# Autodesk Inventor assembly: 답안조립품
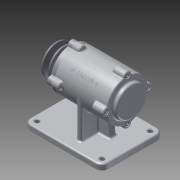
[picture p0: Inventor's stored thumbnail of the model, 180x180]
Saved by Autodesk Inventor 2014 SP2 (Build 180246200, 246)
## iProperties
Created: 2015-12
Part Number: 답안조립품
Document SubType Name: Assembly
Designer: Administrator
Author: Administrator
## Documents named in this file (11)
- C:\Users\Administrator\Desktop\451207V1017\답안조립품.iam
- C:\Users\Administrator\Desktop\451207V1017\본체.ipt
- C:\Users\Administrator\Desktop\451207V1017\커버.ipt
- C:\Users\Administrator\Desktop\451207V1017\커버2.ipt
- C:\Users\Administrator\Desktop\451207V1017\베어링 6204.ipt
- C:\Users\Administrator\Desktop\451207V1017\축.ipt
- C:\Users\Administrator\Desktop\451207V1017\오일실.ipt
- C:\Users\Administrator\Desktop\451207V1017\키(4 x 4 x 12).ipt
- C:\Users\Administrator\Desktop\451207V1017\V-벨트풀리.ipt
- C:\Users\Administrator\Desktop\451207V1017\너트 M12x1.25.ipt
- C:\Users\Administrator\Desktop\451207V1017\볼트 M4 x 12.ipt
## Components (6 placed, 5 different names)
1. KS B 2023 6204 - 20 x 47 x 14:1
2. KS B 2023 6204 - 20 x 47 x 14:2
3. KS B 2804 D D - 20 32 8:1
4. KS B 1311 (I) 4 x 4 x 12:1
5. V-벨트풀리:1
6. KS B 1012 클래스 1 일반 - 미터 M12x1.25:1
